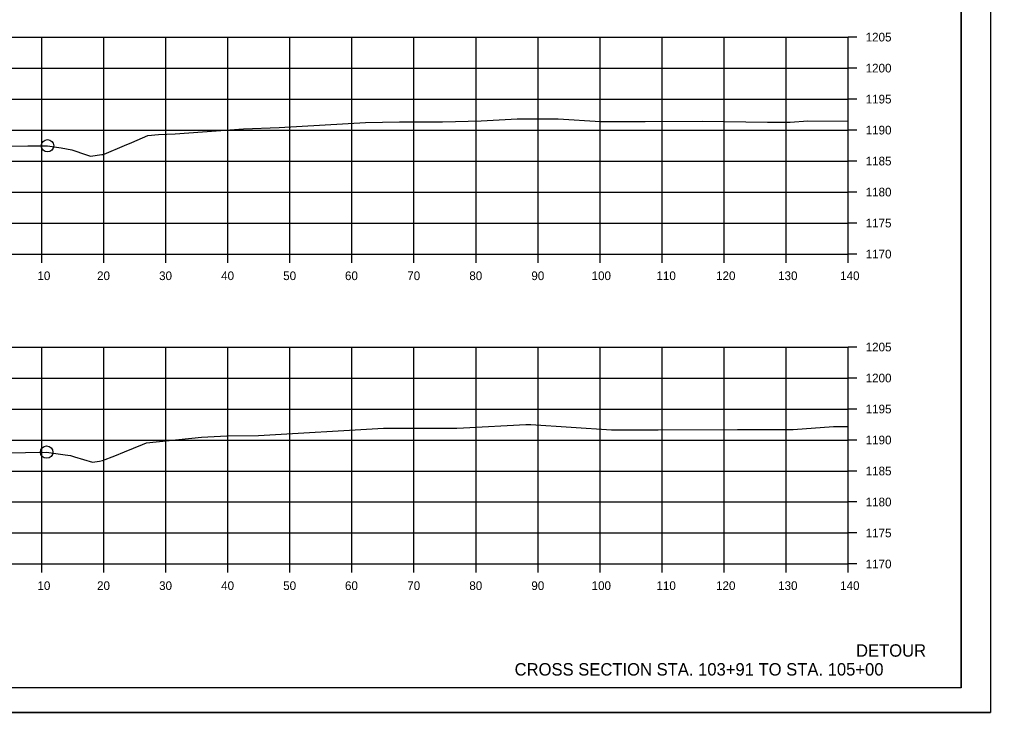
# Model space of a CAD drawing. Extents: x 1368971 to 1374497, y 378717 to 381839.
# Drawn here: x 1371269 to 1371425.6, y 380772.8 to 380884.6 of the extents above; entities that cross this region are included whole.
import ezdxf

# ---------------------------------------------------------------- set-up
doc = ezdxf.new("R2010")
doc.units = 0
for name, color, linetype in [('R_Axis', 7, 'Continuous'), ('R_Axis Annot', 7, 'Continuous'), ('R_Draft', 7, 'Continuous'), ('R_Exist Surface', 7, 'Continuous'), ('R_Grid', 7, 'Continuous'), ('R_No Plot', 7, 'Continuous')]:
    doc.layers.add(name, color=color, linetype=linetype)

msp = doc.modelspace()

# ---------------------------------------------------------------- linework, layer by layer
at = {"layer": 'R_Axis'}
for p, q in [((1371402.64, 380846.73), (1371402.64, 380881.73)), ((1371404.04, 380881.73), (1371402.64, 380881.73)), ((1371404.04, 380876.73), (1371402.64, 380876.73)), ((1371404.04, 380871.73), (1371402.64, 380871.73)), ((1371404.04, 380866.73), (1371402.64, 380866.73)), ((1371404.04, 380861.73), (1371402.64, 380861.73)), ((1371404.04, 380856.73), (1371402.64, 380856.73)), ((1371404.04, 380851.73), (1371402.64, 380851.73)), ((1371122.64, 380846.73), (1371402.64, 380846.73)), ((1371272.64, 380845.33), (1371272.64, 380846.73)), ((1371282.64, 380845.33), (1371282.64, 380846.73)), ((1371292.64, 380845.33), (1371292.64, 380846.73)), ((1371302.64, 380845.33), (1371302.64, 380846.73)), ((1371312.64, 380845.33), (1371312.64, 380846.73)), ((1371322.64, 380845.33), (1371322.64, 380846.73)), ((1371332.64, 380845.33), (1371332.64, 380846.73)), ((1371342.64, 380845.33), (1371342.64, 380846.73)), ((1371352.64, 380845.33), (1371352.64, 380846.73)), ((1371362.64, 380845.33), (1371362.64, 380846.73)), ((1371372.64, 380845.33), (1371372.64, 380846.73)), ((1371382.64, 380845.33), (1371382.64, 380846.73)), ((1371392.64, 380845.33), (1371392.64, 380846.73)), ((1371402.64, 380845.33), (1371402.64, 380846.73)), ((1371404.04, 380846.73), (1371402.64, 380846.73)), ((1371402.64, 380796.73), (1371402.64, 380831.73)), ((1371404.04, 380831.73), (1371402.64, 380831.73)), ((1371404.04, 380826.73), (1371402.64, 380826.73)), ((1371404.04, 380821.73), (1371402.64, 380821.73)), ((1371404.04, 380816.73), (1371402.64, 380816.73)), ((1371404.04, 380811.73), (1371402.64, 380811.73)), ((1371404.04, 380806.73), (1371402.64, 380806.73)), ((1371404.04, 380801.73), (1371402.64, 380801.73)), ((1371122.64, 380796.73), (1371402.64, 380796.73)), ((1371272.64, 380795.33), (1371272.64, 380796.73)), ((1371282.64, 380795.33), (1371282.64, 380796.73)), ((1371292.64, 380795.33), (1371292.64, 380796.73)), ((1371302.64, 380795.33), (1371302.64, 380796.73)), ((1371312.64, 380795.33), (1371312.64, 380796.73)), ((1371322.64, 380795.33), (1371322.64, 380796.73)), ((1371332.64, 380795.33), (1371332.64, 380796.73)), ((1371342.64, 380795.33), (1371342.64, 380796.73)), ((1371352.64, 380795.33), (1371352.64, 380796.73)), ((1371362.64, 380795.33), (1371362.64, 380796.73)), ((1371372.64, 380795.33), (1371372.64, 380796.73)), ((1371382.64, 380795.33), (1371382.64, 380796.73)), ((1371392.64, 380795.33), (1371392.64, 380796.73)), ((1371402.64, 380795.33), (1371402.64, 380796.73)), ((1371404.04, 380796.73), (1371402.64, 380796.73))]:
    msp.add_line(p, q, dxfattribs=at)
at = {"layer": 'R_Exist Surface'}
for points in [[(1371262.54, 380864.06), (1371270.4, 380864.17), (1371273.57, 380864.21), (1371275.8, 380863.87), (1371277.49, 380863.57), (1371279.85, 380862.75), (1371280.52, 380862.54), (1371282.33, 380862.77), (1371282.59, 380862.79), (1371282.7, 380862.85), (1371285.96, 380864.23), (1371287.16, 380864.71), (1371289.73, 380865.84), (1371291.45, 380866.01), (1371294.13, 380866.13), (1371305.18, 380866.91), (1371310.93, 380867.13), (1371324.8, 380867.93), (1371330.31, 380868.08), (1371337.26, 380868.05), (1371343.49, 380868.23), (1371349.28, 380868.53), (1371355.86, 380868.55), (1371362.7, 380868.1), (1371369.93, 380868.13), (1371379.2, 380868.17), (1371389.63, 380868.03), (1371393.25, 380868.03), (1371396.11, 380868.24), (1371402.64, 380868.15)], [(1371266.62, 380814.68), (1371273.43, 380814.78), (1371276.43, 380814.33), (1371277.27, 380814.22), (1371277.91, 380814.04), (1371280.8, 380813.14), (1371281.98, 380813.29), (1371282.46, 380813.4), (1371284.44, 380814.2), (1371285.96, 380814.84), (1371288.86, 380816.02), (1371289.51, 380816.3), (1371298.39, 380817.2), (1371302.47, 380817.39), (1371307.6, 380817.47), (1371327.73, 380818.65), (1371328.55, 380818.66), (1371339.54, 380818.65), (1371340.64, 380818.71), (1371350.65, 380819.25), (1371351.45, 380819.23), (1371364.49, 380818.38), (1371364.7, 380818.37), (1371372.02, 380818.39), (1371384.81, 380818.44), (1371385.59, 380818.43), (1371393.75, 380818.45), (1371400.27, 380818.93), (1371402.13, 380818.91), (1371402.64, 380818.9)]]:
    msp.add_lwpolyline(points, dxfattribs=at)
at = {"layer": 'R_Grid'}
for p, q in [((1371122.64, 380881.73), (1371402.64, 380881.73)), ((1371272.64, 380846.73), (1371272.64, 380881.73)), ((1371282.64, 380846.73), (1371282.64, 380881.73)), ((1371292.64, 380846.73), (1371292.64, 380881.73)), ((1371302.64, 380846.73), (1371302.64, 380881.73)), ((1371312.64, 380846.73), (1371312.64, 380881.73)), ((1371322.64, 380846.73), (1371322.64, 380881.73)), ((1371332.64, 380846.73), (1371332.64, 380881.73)), ((1371342.64, 380846.73), (1371342.64, 380881.73)), ((1371352.64, 380846.73), (1371352.64, 380881.73)), ((1371362.64, 380846.73), (1371362.64, 380881.73)), ((1371372.64, 380846.73), (1371372.64, 380881.73)), ((1371382.64, 380846.73), (1371382.64, 380881.73)), ((1371392.64, 380846.73), (1371392.64, 380881.73)), ((1371402.64, 380846.73), (1371402.64, 380881.73)), ((1371122.64, 380876.73), (1371402.64, 380876.73)), ((1371122.64, 380871.73), (1371402.64, 380871.73)), ((1371122.64, 380866.73), (1371402.64, 380866.73)), ((1371122.64, 380861.73), (1371402.64, 380861.73)), ((1371122.64, 380856.73), (1371402.64, 380856.73)), ((1371122.64, 380851.73), (1371402.64, 380851.73)), ((1371122.64, 380846.73), (1371402.64, 380846.73)), ((1371122.64, 380831.73), (1371402.64, 380831.73)), ((1371272.64, 380796.73), (1371272.64, 380831.73)), ((1371282.64, 380796.73), (1371282.64, 380831.73)), ((1371292.64, 380796.73), (1371292.64, 380831.73)), ((1371302.64, 380796.73), (1371302.64, 380831.73)), ((1371312.64, 380796.73), (1371312.64, 380831.73)), ((1371322.64, 380796.73), (1371322.64, 380831.73)), ((1371332.64, 380796.73), (1371332.64, 380831.73)), ((1371342.64, 380796.73), (1371342.64, 380831.73)), ((1371352.64, 380796.73), (1371352.64, 380831.73)), ((1371362.64, 380796.73), (1371362.64, 380831.73)), ((1371372.64, 380796.73), (1371372.64, 380831.73)), ((1371382.64, 380796.73), (1371382.64, 380831.73)), ((1371392.64, 380796.73), (1371392.64, 380831.73)), ((1371402.64, 380796.73), (1371402.64, 380831.73)), ((1371122.64, 380826.73), (1371402.64, 380826.73)), ((1371122.64, 380821.73), (1371402.64, 380821.73)), ((1371122.64, 380816.73), (1371402.64, 380816.73)), ((1371122.64, 380811.73), (1371402.64, 380811.73)), ((1371122.64, 380806.73), (1371402.64, 380806.73)), ((1371122.64, 380801.73), (1371402.64, 380801.73)), ((1371122.64, 380796.73), (1371402.64, 380796.73))]:
    msp.add_line(p, q, dxfattribs=at)
at = {"layer": 'R_No Plot'}
for p, q in [((1371420.82, 380776.73), (1371420.82, 380982.19)), ((1371420.82, 380776.73), (1371104.64, 380776.73)), ((1371092.24, 380772.76), (1371425.58, 380772.76))]:
    msp.add_line(p, q, dxfattribs=at)
for points in [[(1371092.24, 380986.09), (1371425.58, 380986.09), (1371425.58, 380772.75), (1371092.24, 380772.75)], [(1371338.56, 380982.19), (1371338.56, 380972.31), (1371374.3, 380972.31), (1371374.3, 380969.39), (1371397.49, 380969.39), (1371397.49, 380946.18), (1371420.82, 380946.18), (1371420.82, 380776.73), (1371104.64, 380776.73), (1371104.64, 380982.19)]]:
    msp.add_lwpolyline(points, close=True, dxfattribs=at)
for centre in [(1371273.57, 380864.21), (1371273.43, 380814.78)]:
    msp.add_circle(centre, 1, dxfattribs=at)

# ---------------------------------------------------------------- texts
at = {"layer": 'R_Axis Annot'}
for s, p in [('1205', (1371405.44, 380881.03)), ('1200', (1371405.44, 380876.03)), ('1195', (1371405.44, 380871.03)), ('1190', (1371405.44, 380866.03)), ('1185', (1371405.44, 380861.03)), ('1180', (1371405.44, 380856.03)), ('1175', (1371405.44, 380851.03)), ('1170', (1371405.44, 380846.03)), ('10', (1371271.95, 380842.53)), ('20', (1371281.56, 380842.53)), ('30', (1371291.56, 380842.53)), ('40', (1371301.56, 380842.53)), ('50', (1371311.56, 380842.53)), ('60', (1371321.52, 380842.53)), ('70', (1371331.56, 380842.53)), ('80', (1371341.56, 380842.53)), ('90', (1371351.56, 380842.53)), ('100', (1371361.27, 380842.53)), ('110', (1371371.72, 380842.53)), ('120', (1371381.33, 380842.53)), ('130', (1371391.33, 380842.53)), ('140', (1371401.33, 380842.53)), ('1205', (1371405.44, 380831.03)), ('1200', (1371405.44, 380826.03)), ('1195', (1371405.44, 380821.03)), ('1190', (1371405.44, 380816.03)), ('1185', (1371405.44, 380811.03)), ('1180', (1371405.44, 380806.03)), ('1175', (1371405.44, 380801.03)), ('1170', (1371405.44, 380796.03)), ('10', (1371271.95, 380792.53)), ('20', (1371281.56, 380792.53)), ('30', (1371291.56, 380792.53)), ('40', (1371301.56, 380792.53)), ('50', (1371311.56, 380792.53)), ('60', (1371321.52, 380792.53)), ('70', (1371331.56, 380792.53)), ('80', (1371341.56, 380792.53)), ('90', (1371351.56, 380792.53)), ('100', (1371361.27, 380792.53)), ('110', (1371371.72, 380792.53)), ('120', (1371381.33, 380792.53)), ('130', (1371391.33, 380792.53)), ('140', (1371401.33, 380792.53))]:
    msp.add_text(s, height=1.4, dxfattribs=at).set_placement(p)
at = {"layer": 'R_Draft'}
for s, p in [('DETOUR', (1371403.89, 380781.77)), ('CROSS SECTION STA. 103+91 TO STA. 105+00', (1371348.86, 380778.73))]:
    msp.add_text(s, height=2, dxfattribs=at).set_placement(p)

doc.saveas('drawing.dxf')
